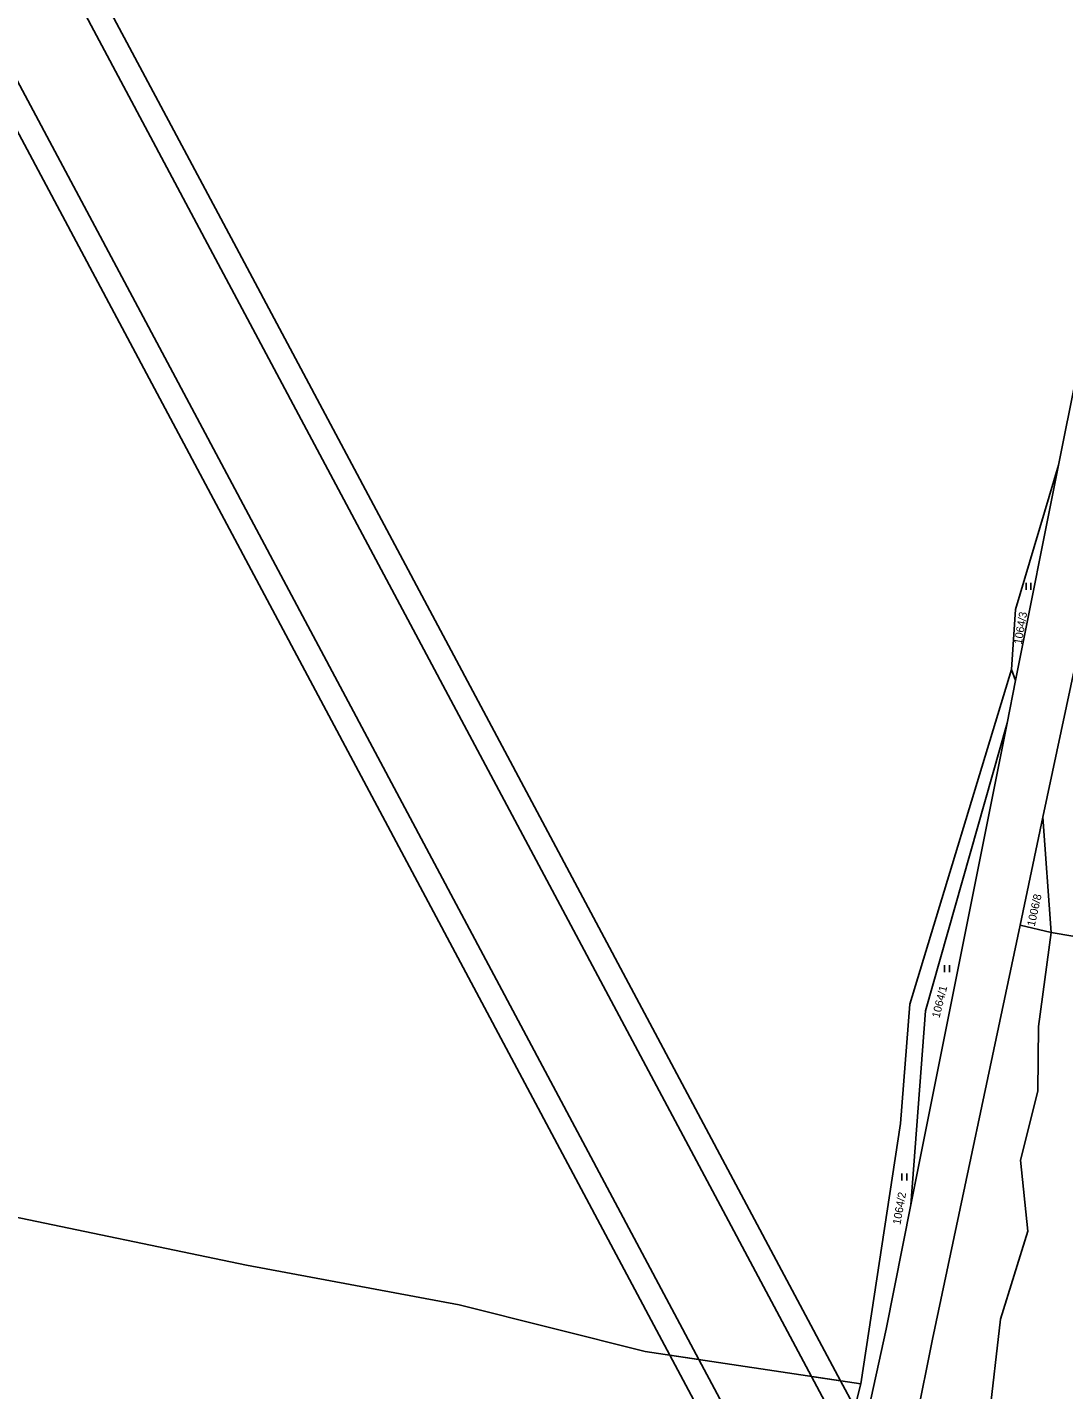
# Model space of a CAD drawing. Extents: x -850689 to -847910, y -1058374 to -1054747.
# Drawn here: x -849820.3 to -849600.1, y -1056733.6 to -1056444.2 of the extents above; entities that cross this region are included whole.
import ezdxf

# ---------------------------------------------------------------- set-up
doc = ezdxf.new("R2010")
doc.units = 0
for name, color, linetype in [('KN_BREMENA', 7, 'Continuous'), ('KN_HRANICE', 7, 'Continuous'), ('KN_KULTURY', 7, 'Continuous'), ('KN_PARCELY', 7, 'Continuous')]:
    doc.layers.add(name, color=color, linetype=linetype)

# ---------------------------------------------------------------- blocks, each defined once
blk = doc.blocks.new('306')
for p, q in [((-0.5, 1.5), (-0.5, 0)), ((0.5, 0), (0.5, 1.5))]:
    blk.add_line(p, q)

msp = doc.modelspace()

# ---------------------------------------------------------------- linework, layer by layer
at = {"layer": 'KN_BREMENA'}
for points in [[(-849780.29, -1056493.37), (-849829.22, -1056401.6), (-849824.05, -1056400.67), (-849775.88, -1056491.02), (-849647.55, -1056731.67), (-849653.71, -1056730.75)], [(-849801.82, -1056504.85), (-849854.46, -1056406.14), (-849849.29, -1056405.21), (-849797.41, -1056502.5), (-849677.61, -1056727.16), (-849683.77, -1056726.23)], [(-849683.77, -1056726.23), (-849677.61, -1056727.16), (-849653.15, -1056773.03), (-849654.26, -1056781.57)], [(-849653.71, -1056730.75), (-849647.55, -1056731.67), (-849644.52, -1056737.36), (-849646.34, -1056744.57)]]:
    msp.add_lwpolyline(points, close=True, dxfattribs=at)
at = {"layer": 'KN_HRANICE'}
for p, q in [((-849601.24, -1056537.2), (-849591.21, -1056486.93)), ((-849578.61, -1056489.59), (-849604.54, -1056611.95)), ((-849610.37, -1056582.92), (-849601.24, -1056537.2)), ((-849610.36, -1056567.83), (-849601.24, -1056537.2)), ((-849611.24, -1056580.57), (-849610.36, -1056567.83)), ((-849632.83, -1056651.68), (-849611.24, -1056580.57)), ((-849611.24, -1056580.57), (-849610.37, -1056582.92)), ((-849612.18, -1056592), (-849610.37, -1056582.92)), ((-849632.6, -1056694.29), (-849612.18, -1056592)), ((-849629.5, -1056653.11), (-849612.18, -1056592)), ((-849604.54, -1056611.95), (-849609.39, -1056634.86)), ((-849602.81, -1056636.44), (-849604.54, -1056611.95)), ((-849609.39, -1056634.86), (-849628.03, -1056722.82)), ((-849602.81, -1056636.44), (-849609.39, -1056634.86)), ((-849605.46, -1056656.43), (-849602.81, -1056636.44)), ((-849602.81, -1056636.44), (-849495.08, -1056654.69)), ((-849634.83, -1056677.01), (-849632.83, -1056651.68)), ((-849632.6, -1056694.29), (-849629.5, -1056653.11)), ((-849605.66, -1056670.13), (-849605.46, -1056656.43)), ((-849609.32, -1056684.79), (-849605.66, -1056670.13)), ((-849643.25, -1056732.32), (-849634.83, -1056677.01)), ((-849607.78, -1056699.85), (-849609.32, -1056684.79)), ((-849857.82, -1056689.66), (-849773.74, -1056707.09)), ((-849637.87, -1056720.7), (-849632.6, -1056694.29)), ((-849613.57, -1056718.57), (-849607.78, -1056699.85)), ((-849773.74, -1056707.09), (-849728.55, -1056715.5)), ((-849728.55, -1056715.5), (-849689.04, -1056725.44)), ((-849613.57, -1056718.57), (-849616.94, -1056748.2)), ((-849637.87, -1056720.7), (-849654.96, -1056798.56)), ((-849652.87, -1056847.29), (-849628.03, -1056722.82)), ((-849689.04, -1056725.44), (-849643.25, -1056732.32)), ((-849643.25, -1056732.32), (-849652.77, -1056770.09))]:
    msp.add_line(p, q, dxfattribs=at)

# ---------------------------------------------------------------- block references
at = {"layer": 'KN_KULTURY'}
for p in [(-849607.61, -1056563.68), (-849624.93, -1056644.87), (-849633.99, -1056689.12)]:
    msp.add_blockref('306', p, dxfattribs=at)

# ---------------------------------------------------------------- texts
at = {"layer": 'KN_PARCELY'}
for s, rotation, p in [('1064/3', 80.214, (-849609.07, -1056575.34)), ('1006/8', 77.521, (-849606.31, -1056635.27)), ('1064/1', 75.917, (-849626.54, -1056654.73)), ('1064/2', 79.87, (-849634.82, -1056698.6))]:
    msp.add_text(s, height=1.7, rotation=rotation, dxfattribs=at).set_placement(p)

doc.saveas('drawing.dxf')
